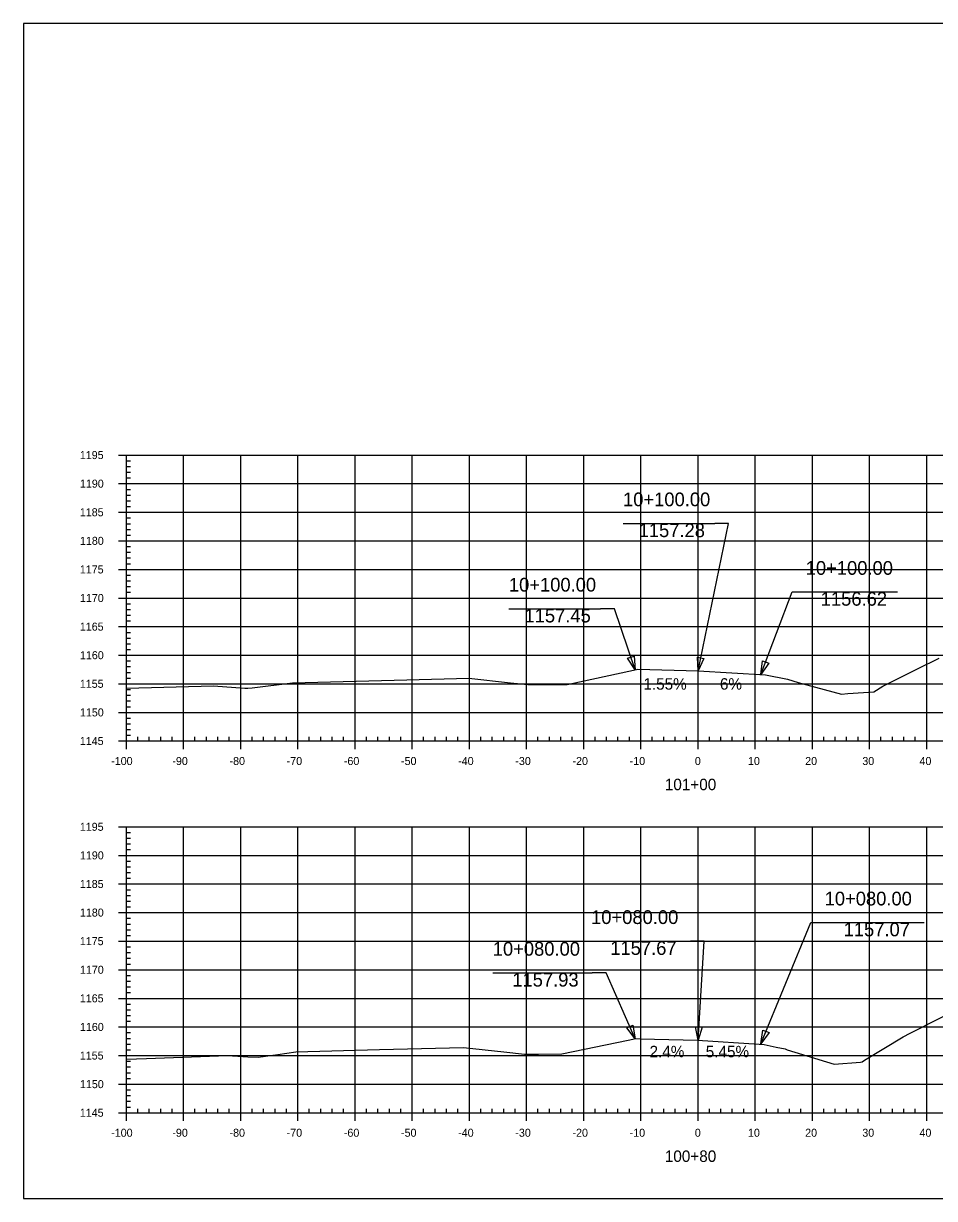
# Model space of a CAD drawing. Extents: x 688474 to 694748, y 765018 to 767373.
# Drawn here: x 689619.8 to 689779.2, y 765584.1 to 765789.5 of the extents above; entities that cross this region are included whole.
import ezdxf

# ---------------------------------------------------------------- set-up
doc = ezdxf.new("R2010")
doc.units = 0
for name, color, linetype in [('60', 7, 'Continuous'), ('Default', 7, 'Continuous'), ('R_Exist Surface', 7, 'Continuous'), ('R_Grid', 7, 'Continuous'), ('R_No Plot', 7, 'Continuous'), ('R_Xsect Slope', 7, 'Continuous')]:
    doc.layers.add(name, color=color, linetype=linetype)

msp = doc.modelspace()

# ---------------------------------------------------------------- linework, layer by layer
at = {"layer": '60'}
for p, q in [((689636.42, 765714.06), (689639.22, 765714.06)), ((689637.82, 765664.06), (689637.82, 765714.06)), ((689637.82, 765713.06), (689638.52, 765713.06)), ((689637.82, 765712.06), (689638.52, 765712.06)), ((689637.82, 765711.06), (689638.52, 765711.06)), ((689636.42, 765709.06), (689639.22, 765709.06)), ((689637.82, 765710.06), (689638.52, 765710.06)), ((689637.82, 765708.06), (689638.52, 765708.06)), ((689637.82, 765707.06), (689638.52, 765707.06)), ((689637.82, 765706.06), (689638.52, 765706.06)), ((689637.82, 765705.06), (689638.52, 765705.06)), ((689636.42, 765704.06), (689639.22, 765704.06)), ((689637.82, 765703.06), (689638.52, 765703.06)), ((689637.82, 765702.06), (689638.52, 765702.06)), ((689637.82, 765701.06), (689638.52, 765701.06)), ((689636.42, 765699.06), (689639.22, 765699.06)), ((689637.82, 765700.06), (689638.52, 765700.06)), ((689637.82, 765698.06), (689638.52, 765698.06)), ((689637.82, 765697.06), (689638.52, 765697.06)), ((689637.82, 765696.06), (689638.52, 765696.06)), ((689636.42, 765694.06), (689639.22, 765694.06)), ((689637.82, 765695.06), (689638.52, 765695.06)), ((689637.82, 765693.06), (689638.52, 765693.06)), ((689637.82, 765692.06), (689638.52, 765692.06)), ((689637.82, 765691.06), (689638.52, 765691.06)), ((689637.82, 765690.06), (689638.52, 765690.06)), ((689636.42, 765689.06), (689639.22, 765689.06)), ((689637.82, 765688.06), (689638.52, 765688.06)), ((689637.82, 765687.06), (689638.52, 765687.06)), ((689637.82, 765686.06), (689638.52, 765686.06)), ((689636.42, 765684.06), (689639.22, 765684.06)), ((689637.82, 765685.06), (689638.52, 765685.06)), ((689637.82, 765683.06), (689638.52, 765683.06)), ((689637.82, 765682.06), (689638.52, 765682.06)), ((689637.82, 765681.06), (689638.52, 765681.06)), ((689637.82, 765680.06), (689638.52, 765680.06)), ((689636.42, 765679.06), (689639.22, 765679.06)), ((689637.82, 765678.06), (689638.52, 765678.06)), ((689637.82, 765677.06), (689638.52, 765677.06)), ((689637.82, 765676.06), (689638.52, 765676.06)), ((689636.42, 765674.06), (689639.22, 765674.06)), ((689637.82, 765675.06), (689638.52, 765675.06)), ((689637.82, 765673.06), (689638.52, 765673.06)), ((689637.82, 765672.06), (689638.52, 765672.06)), ((689637.82, 765671.06), (689638.52, 765671.06)), ((689637.82, 765670.06), (689638.52, 765670.06)), ((689636.42, 765669.06), (689639.22, 765669.06)), ((689637.82, 765668.06), (689638.52, 765668.06)), ((689637.82, 765667.06), (689638.52, 765667.06)), ((689637.82, 765666.06), (689638.52, 765666.06)), ((689637.82, 765662.66), (689637.82, 765665.46)), ((689647.82, 765662.66), (689647.82, 765665.46)), ((689657.82, 765662.66), (689657.82, 765665.46)), ((689667.82, 765662.66), (689667.82, 765665.46)), ((689677.82, 765662.66), (689677.82, 765665.46)), ((689687.82, 765662.66), (689687.82, 765665.46)), ((689697.82, 765662.66), (689697.82, 765665.46)), ((689707.82, 765662.66), (689707.82, 765665.46)), ((689717.82, 765662.66), (689717.82, 765665.46)), ((689727.82, 765662.66), (689727.82, 765665.46)), ((689737.82, 765662.66), (689737.82, 765665.46)), ((689747.82, 765662.66), (689747.82, 765665.46)), ((689757.82, 765662.66), (689757.82, 765665.46)), ((689767.82, 765662.66), (689767.82, 765665.46)), ((689777.82, 765662.66), (689777.82, 765665.46)), ((689636.42, 765664.06), (689639.22, 765664.06)), ((689637.82, 765665.06), (689638.52, 765665.06)), ((689637.82, 765664.06), (689837.82, 765664.06)), ((689639.82, 765664.06), (689639.82, 765664.76)), ((689641.82, 765664.06), (689641.82, 765664.76)), ((689643.82, 765664.06), (689643.82, 765664.76)), ((689645.82, 765664.06), (689645.82, 765664.76)), ((689649.82, 765664.06), (689649.82, 765664.76)), ((689651.82, 765664.06), (689651.82, 765664.76)), ((689653.82, 765664.06), (689653.82, 765664.76)), ((689655.82, 765664.06), (689655.82, 765664.76)), ((689659.82, 765664.06), (689659.82, 765664.76)), ((689661.82, 765664.06), (689661.82, 765664.76)), ((689663.82, 765664.06), (689663.82, 765664.76)), ((689665.82, 765664.06), (689665.82, 765664.76)), ((689669.82, 765664.06), (689669.82, 765664.76)), ((689671.82, 765664.06), (689671.82, 765664.76)), ((689673.82, 765664.06), (689673.82, 765664.76)), ((689675.82, 765664.06), (689675.82, 765664.76)), ((689679.82, 765664.06), (689679.82, 765664.76)), ((689681.82, 765664.06), (689681.82, 765664.76)), ((689683.82, 765664.06), (689683.82, 765664.76)), ((689685.82, 765664.06), (689685.82, 765664.76)), ((689689.82, 765664.06), (689689.82, 765664.76)), ((689691.82, 765664.06), (689691.82, 765664.76)), ((689693.82, 765664.06), (689693.82, 765664.76)), ((689695.82, 765664.06), (689695.82, 765664.76)), ((689699.82, 765664.06), (689699.82, 765664.76)), ((689701.82, 765664.06), (689701.82, 765664.76)), ((689703.82, 765664.06), (689703.82, 765664.76)), ((689705.82, 765664.06), (689705.82, 765664.76)), ((689709.82, 765664.06), (689709.82, 765664.76)), ((689711.82, 765664.06), (689711.82, 765664.76)), ((689713.82, 765664.06), (689713.82, 765664.76)), ((689715.82, 765664.06), (689715.82, 765664.76)), ((689719.82, 765664.06), (689719.82, 765664.76)), ((689721.82, 765664.06), (689721.82, 765664.76)), ((689723.82, 765664.06), (689723.82, 765664.76)), ((689725.82, 765664.06), (689725.82, 765664.76)), ((689729.82, 765664.06), (689729.82, 765664.76)), ((689731.82, 765664.06), (689731.82, 765664.76)), ((689733.82, 765664.06), (689733.82, 765664.76)), ((689735.82, 765664.06), (689735.82, 765664.76)), ((689739.82, 765664.06), (689739.82, 765664.76)), ((689741.82, 765664.06), (689741.82, 765664.76)), ((689743.82, 765664.06), (689743.82, 765664.76)), ((689745.82, 765664.06), (689745.82, 765664.76)), ((689749.82, 765664.06), (689749.82, 765664.76)), ((689751.82, 765664.06), (689751.82, 765664.76)), ((689753.82, 765664.06), (689753.82, 765664.76)), ((689755.82, 765664.06), (689755.82, 765664.76)), ((689759.82, 765664.06), (689759.82, 765664.76)), ((689761.82, 765664.06), (689761.82, 765664.76)), ((689763.82, 765664.06), (689763.82, 765664.76)), ((689765.82, 765664.06), (689765.82, 765664.76)), ((689769.82, 765664.06), (689769.82, 765664.76)), ((689771.82, 765664.06), (689771.82, 765664.76)), ((689773.82, 765664.06), (689773.82, 765664.76)), ((689775.82, 765664.06), (689775.82, 765664.76)), ((689636.42, 765649.06), (689639.22, 765649.06)), ((689637.82, 765599.06), (689637.82, 765649.06)), ((689637.82, 765648.06), (689638.52, 765648.06)), ((689637.82, 765647.06), (689638.52, 765647.06)), ((689637.82, 765646.06), (689638.52, 765646.06)), ((689637.82, 765645.06), (689638.52, 765645.06)), ((689636.42, 765644.06), (689639.22, 765644.06)), ((689637.82, 765643.06), (689638.52, 765643.06)), ((689637.82, 765642.06), (689638.52, 765642.06)), ((689637.82, 765641.06), (689638.52, 765641.06)), ((689636.42, 765639.06), (689639.22, 765639.06)), ((689637.82, 765640.06), (689638.52, 765640.06)), ((689637.82, 765638.06), (689638.52, 765638.06)), ((689637.82, 765637.06), (689638.52, 765637.06)), ((689637.82, 765636.06), (689638.52, 765636.06)), ((689637.82, 765635.06), (689638.52, 765635.06)), ((689636.42, 765634.06), (689639.22, 765634.06)), ((689637.82, 765633.06), (689638.52, 765633.06)), ((689637.82, 765632.06), (689638.52, 765632.06)), ((689637.82, 765631.06), (689638.52, 765631.06)), ((689636.42, 765629.06), (689639.22, 765629.06)), ((689637.82, 765630.06), (689638.52, 765630.06)), ((689637.82, 765628.06), (689638.52, 765628.06)), ((689637.82, 765627.06), (689638.52, 765627.06)), ((689637.82, 765626.06), (689638.52, 765626.06)), ((689637.82, 765625.06), (689638.52, 765625.06)), ((689636.42, 765624.06), (689639.22, 765624.06)), ((689637.82, 765623.06), (689638.52, 765623.06)), ((689637.82, 765622.06), (689638.52, 765622.06)), ((689637.82, 765621.06), (689638.52, 765621.06)), ((689637.82, 765620.06), (689638.52, 765620.06)), ((689636.42, 765619.06), (689639.22, 765619.06)), ((689637.82, 765618.06), (689638.52, 765618.06)), ((689637.82, 765617.06), (689638.52, 765617.06)), ((689637.82, 765616.06), (689638.52, 765616.06)), ((689636.42, 765614.06), (689639.22, 765614.06)), ((689637.82, 765615.06), (689638.52, 765615.06)), ((689637.82, 765613.06), (689638.52, 765613.06)), ((689637.82, 765612.06), (689638.52, 765612.06)), ((689637.82, 765611.06), (689638.52, 765611.06)), ((689637.82, 765610.06), (689638.52, 765610.06)), ((689636.42, 765609.06), (689639.22, 765609.06)), ((689637.82, 765608.06), (689638.52, 765608.06)), ((689637.82, 765607.06), (689638.52, 765607.06)), ((689637.82, 765606.06), (689638.52, 765606.06)), ((689636.42, 765604.06), (689639.22, 765604.06)), ((689637.82, 765605.06), (689638.52, 765605.06)), ((689637.82, 765603.06), (689638.52, 765603.06)), ((689637.82, 765602.06), (689638.52, 765602.06)), ((689637.82, 765601.06), (689638.52, 765601.06)), ((689637.82, 765597.66), (689637.82, 765600.46)), ((689637.82, 765600.06), (689638.52, 765600.06)), ((689639.82, 765599.06), (689639.82, 765599.76)), ((689641.82, 765599.06), (689641.82, 765599.76)), ((689643.82, 765599.06), (689643.82, 765599.76)), ((689645.82, 765599.06), (689645.82, 765599.76)), ((689647.82, 765597.66), (689647.82, 765600.46)), ((689649.82, 765599.06), (689649.82, 765599.76)), ((689651.82, 765599.06), (689651.82, 765599.76)), ((689653.82, 765599.06), (689653.82, 765599.76)), ((689655.82, 765599.06), (689655.82, 765599.76)), ((689657.82, 765597.66), (689657.82, 765600.46)), ((689659.82, 765599.06), (689659.82, 765599.76)), ((689661.82, 765599.06), (689661.82, 765599.76)), ((689663.82, 765599.06), (689663.82, 765599.76)), ((689665.82, 765599.06), (689665.82, 765599.76)), ((689667.82, 765597.66), (689667.82, 765600.46)), ((689669.82, 765599.06), (689669.82, 765599.76)), ((689671.82, 765599.06), (689671.82, 765599.76)), ((689673.82, 765599.06), (689673.82, 765599.76)), ((689675.82, 765599.06), (689675.82, 765599.76)), ((689677.82, 765597.66), (689677.82, 765600.46)), ((689679.82, 765599.06), (689679.82, 765599.76)), ((689681.82, 765599.06), (689681.82, 765599.76)), ((689683.82, 765599.06), (689683.82, 765599.76)), ((689685.82, 765599.06), (689685.82, 765599.76)), ((689687.82, 765597.66), (689687.82, 765600.46)), ((689689.82, 765599.06), (689689.82, 765599.76)), ((689691.82, 765599.06), (689691.82, 765599.76)), ((689693.82, 765599.06), (689693.82, 765599.76)), ((689695.82, 765599.06), (689695.82, 765599.76)), ((689697.82, 765597.66), (689697.82, 765600.46)), ((689699.82, 765599.06), (689699.82, 765599.76)), ((689701.82, 765599.06), (689701.82, 765599.76)), ((689703.82, 765599.06), (689703.82, 765599.76)), ((689705.82, 765599.06), (689705.82, 765599.76)), ((689707.82, 765597.66), (689707.82, 765600.46)), ((689709.82, 765599.06), (689709.82, 765599.76)), ((689711.82, 765599.06), (689711.82, 765599.76)), ((689713.82, 765599.06), (689713.82, 765599.76)), ((689715.82, 765599.06), (689715.82, 765599.76)), ((689717.82, 765597.66), (689717.82, 765600.46)), ((689719.82, 765599.06), (689719.82, 765599.76)), ((689721.82, 765599.06), (689721.82, 765599.76)), ((689723.82, 765599.06), (689723.82, 765599.76)), ((689725.82, 765599.06), (689725.82, 765599.76)), ((689727.82, 765597.66), (689727.82, 765600.46)), ((689729.82, 765599.06), (689729.82, 765599.76)), ((689731.82, 765599.06), (689731.82, 765599.76)), ((689733.82, 765599.06), (689733.82, 765599.76)), ((689735.82, 765599.06), (689735.82, 765599.76)), ((689737.82, 765597.66), (689737.82, 765600.46)), ((689739.82, 765599.06), (689739.82, 765599.76)), ((689741.82, 765599.06), (689741.82, 765599.76)), ((689743.82, 765599.06), (689743.82, 765599.76)), ((689745.82, 765599.06), (689745.82, 765599.76)), ((689747.82, 765597.66), (689747.82, 765600.46)), ((689749.82, 765599.06), (689749.82, 765599.76)), ((689751.82, 765599.06), (689751.82, 765599.76)), ((689753.82, 765599.06), (689753.82, 765599.76)), ((689755.82, 765599.06), (689755.82, 765599.76)), ((689757.82, 765597.66), (689757.82, 765600.46)), ((689759.82, 765599.06), (689759.82, 765599.76)), ((689761.82, 765599.06), (689761.82, 765599.76)), ((689763.82, 765599.06), (689763.82, 765599.76)), ((689765.82, 765599.06), (689765.82, 765599.76)), ((689767.82, 765597.66), (689767.82, 765600.46)), ((689769.82, 765599.06), (689769.82, 765599.76)), ((689771.82, 765599.06), (689771.82, 765599.76)), ((689773.82, 765599.06), (689773.82, 765599.76)), ((689775.82, 765599.06), (689775.82, 765599.76)), ((689777.82, 765597.66), (689777.82, 765600.46)), ((689636.42, 765599.06), (689639.22, 765599.06)), ((689637.82, 765599.06), (689837.82, 765599.06))]:
    msp.add_line(p, q, dxfattribs=at)
at = {"layer": 'R_Exist Surface'}
for p, q in [((689724.7, 765702.11), (689740.75, 765702.11)), ((689756.66, 765690.12), (689772.71, 765690.12)), ((689704.73, 765687.19), (689720.78, 765687.19)), ((689759.97, 765632.31), (689777.39, 765632.31)), ((689719.11, 765629.06), (689736.52, 765629.06)), ((689701.91, 765623.52), (689719.33, 765623.52))]:
    msp.add_line(p, q, dxfattribs=at)
for points in [[(689737.82, 765676.34), (689743.15, 765702.11), (689740.75, 765702.11)], [(689748.82, 765675.68), (689754.26, 765690.12), (689756.66, 765690.12)], [(689726.82, 765676.52), (689723.18, 765687.19), (689720.78, 765687.19)], [(689637.82, 765673.28), (689653.03, 765673.69), (689658.55, 765673.31), (689659.04, 765673.27), (689659.85, 765673.36), (689666.9, 765674.22), (689686.88, 765674.76), (689697.71, 765675.05), (689705, 765674.25), (689708.07, 765673.92), (689712.74, 765673.93), (689714.95, 765673.92), (689726.53, 765676.45), (689727.27, 765676.61), (689737.82, 765676.34), (689749.65, 765675.63), (689749.65, 765675.63), (689753.45, 765674.85), (689755.33, 765674.28), (689762.91, 765672.26), (689764.04, 765672.35), (689768.57, 765672.67), (689770.15, 765673.63), (689776.24, 765676.65), (689780, 765678.55)], [(689748.82, 765611.13), (689757.57, 765632.31), (689759.97, 765632.31)], [(689737.82, 765611.73), (689738.92, 765629.06), (689736.52, 765629.06)], [(689726.82, 765611.99), (689721.73, 765623.52), (689719.33, 765623.52)], [(689637.82, 765608.4), (689641.32, 765608.55), (689655.51, 765609.05), (689659.04, 765608.86), (689660.9, 765608.79), (689664.34, 765609.24), (689667.46, 765609.68), (689682.09, 765610.09), (689696.81, 765610.49), (689703.82, 765609.71), (689707.49, 765609.31), (689709.91, 765609.32), (689714, 765609.35), (689725.62, 765611.74), (689726.95, 765612.02), (689727.72, 765612), (689737.7, 765611.74), (689748.53, 765611.06), (689749.37, 765611.01), (689751.49, 765610.55), (689753.05, 765610.21), (689753.43, 765610.07), (689761.61, 765607.57), (689766.24, 765607.92), (689766.51, 765607.94), (689766.96, 765608.27), (689773.73, 765612.35), (689774.93, 765612.96), (689790.39, 765620.76)]]:
    msp.add_lwpolyline(points, dxfattribs=at)
for points in [[(689726.82, 765676.52), (689725.51, 765678.53), (689726.62, 765678.91)], [(689737.82, 765676.34), (689737.72, 765678.74), (689738.86, 765678.5)], [(689748.82, 765675.68), (689749.09, 765678.07), (689750.18, 765677.66)], [(689726.82, 765611.99), (689725.34, 765613.89), (689726.41, 765614.36)], [(689737.82, 765611.73), (689737.38, 765614.09), (689738.55, 765614.02)], [(689748.82, 765611.13), (689749.17, 765613.5), (689750.24, 765613.06)]]:
    msp.add_lwpolyline(points, close=True, dxfattribs=at)
at = {"layer": 'R_Grid'}
for p, q in [((689637.82, 765714.06), (689837.82, 765714.06)), ((689637.82, 765664.06), (689637.82, 765714.06)), ((689647.82, 765664.06), (689647.82, 765714.06)), ((689657.82, 765664.06), (689657.82, 765714.06)), ((689667.82, 765664.06), (689667.82, 765714.06)), ((689677.82, 765664.06), (689677.82, 765714.06)), ((689687.82, 765664.06), (689687.82, 765714.06)), ((689697.82, 765664.06), (689697.82, 765714.06)), ((689707.82, 765664.06), (689707.82, 765714.06)), ((689717.82, 765664.06), (689717.82, 765714.06)), ((689727.82, 765664.06), (689727.82, 765714.06)), ((689737.82, 765664.06), (689737.82, 765714.06)), ((689747.82, 765664.06), (689747.82, 765714.06)), ((689757.82, 765664.06), (689757.82, 765714.06)), ((689767.82, 765664.06), (689767.82, 765714.06)), ((689777.82, 765664.06), (689777.82, 765714.06)), ((689637.82, 765709.06), (689837.82, 765709.06)), ((689637.82, 765704.06), (689837.82, 765704.06)), ((689637.82, 765699.06), (689837.82, 765699.06)), ((689637.82, 765694.06), (689837.82, 765694.06)), ((689637.82, 765689.06), (689837.82, 765689.06)), ((689637.82, 765684.06), (689837.82, 765684.06)), ((689637.82, 765679.06), (689837.82, 765679.06)), ((689637.82, 765674.06), (689837.82, 765674.06)), ((689637.82, 765669.06), (689837.82, 765669.06)), ((689637.82, 765664.06), (689837.82, 765664.06)), ((689637.82, 765649.06), (689837.82, 765649.06)), ((689637.82, 765599.06), (689637.82, 765649.06)), ((689647.82, 765599.06), (689647.82, 765649.06)), ((689657.82, 765599.06), (689657.82, 765649.06)), ((689667.82, 765599.06), (689667.82, 765649.06)), ((689677.82, 765599.06), (689677.82, 765649.06)), ((689687.82, 765599.06), (689687.82, 765649.06)), ((689697.82, 765599.06), (689697.82, 765649.06)), ((689707.82, 765599.06), (689707.82, 765649.06)), ((689717.82, 765599.06), (689717.82, 765649.06)), ((689727.82, 765599.06), (689727.82, 765649.06)), ((689737.82, 765599.06), (689737.82, 765649.06)), ((689747.82, 765599.06), (689747.82, 765649.06)), ((689757.82, 765599.06), (689757.82, 765649.06)), ((689767.82, 765599.06), (689767.82, 765649.06)), ((689777.82, 765599.06), (689777.82, 765649.06)), ((689637.82, 765644.06), (689837.82, 765644.06)), ((689637.82, 765639.06), (689837.82, 765639.06)), ((689637.82, 765634.06), (689837.82, 765634.06)), ((689637.82, 765629.06), (689837.82, 765629.06)), ((689637.82, 765624.06), (689837.82, 765624.06)), ((689637.82, 765619.06), (689837.82, 765619.06)), ((689637.82, 765614.06), (689837.82, 765614.06)), ((689637.82, 765609.06), (689837.82, 765609.06)), ((689637.82, 765604.06), (689837.82, 765604.06)), ((689637.82, 765599.06), (689837.82, 765599.06))]:
    msp.add_line(p, q, dxfattribs=at)
at = {"layer": 'R_No Plot'}
msp.add_lwpolyline([(689619.82, 765584.06), (689936, 765584.06), (689936, 765789.52), (689619.82, 765789.52)], close=True, dxfattribs=at)

# ---------------------------------------------------------------- texts
at = {"layer": '60'}
for s, height, p in [('1195', 1.4, (689629.67, 765713.36)), ('1190', 1.4, (689629.69, 765708.36)), ('1185', 1.4, (689629.67, 765703.36)), ('1180', 1.4, (689629.69, 765698.36)), ('1175', 1.4, (689629.67, 765693.36)), ('1170', 1.4, (689629.69, 765688.36)), ('1165', 1.4, (689629.67, 765683.36)), ('1160', 1.4, (689629.69, 765678.36)), ('1155', 1.4, (689629.67, 765673.36)), ('1150', 1.4, (689629.69, 765668.36)), ('1145', 1.4, (689629.67, 765663.36)), ('-100', 1.4, (689635.16, 765659.86)), ('-90', 1.4, (689645.86, 765659.86)), ('-80', 1.4, (689655.86, 765659.86)), ('-70', 1.4, (689665.86, 765659.86)), ('-60', 1.4, (689675.86, 765659.86)), ('-50', 1.4, (689685.86, 765659.86)), ('-40', 1.4, (689695.86, 765659.86)), ('-30', 1.4, (689705.86, 765659.86)), ('-20', 1.4, (689715.86, 765659.86)), ('-10', 1.4, (689725.86, 765659.86)), ('0', 1.4, (689737.26, 765659.86)), ('10', 1.4, (689746.56, 765659.86)), ('20', 1.4, (689756.56, 765659.86)), ('30', 1.4, (689766.56, 765659.86)), ('40', 1.4, (689776.56, 765659.86)), ('101+00', 2, (689732.01, 765655.46)), ('1195', 1.4, (689629.67, 765648.36)), ('1190', 1.4, (689629.69, 765643.36)), ('1185', 1.4, (689629.67, 765638.36)), ('1180', 1.4, (689629.69, 765633.36)), ('1175', 1.4, (689629.67, 765628.36)), ('1170', 1.4, (689629.69, 765623.36)), ('1165', 1.4, (689629.67, 765618.36)), ('1160', 1.4, (689629.69, 765613.36)), ('1155', 1.4, (689629.67, 765608.36)), ('1150', 1.4, (689629.69, 765603.36)), ('1145', 1.4, (689629.67, 765598.36)), ('-100', 1.4, (689635.16, 765594.86)), ('-90', 1.4, (689645.86, 765594.86)), ('-80', 1.4, (689655.86, 765594.86)), ('-70', 1.4, (689665.86, 765594.86)), ('-60', 1.4, (689675.86, 765594.86)), ('-50', 1.4, (689685.86, 765594.86)), ('-40', 1.4, (689695.86, 765594.86)), ('-30', 1.4, (689705.86, 765594.86)), ('-20', 1.4, (689715.86, 765594.86)), ('-10', 1.4, (689725.86, 765594.86)), ('0', 1.4, (689737.26, 765594.86)), ('10', 1.4, (689746.56, 765594.86)), ('20', 1.4, (689756.56, 765594.86)), ('30', 1.4, (689766.56, 765594.86)), ('40', 1.4, (689776.56, 765594.86)), ('100+80', 2, (689732.01, 765590.46))]:
    msp.add_text(s, height=height, dxfattribs=at).set_placement(p)
at = {"layer": 'Default'}
for s, p in [('1.55%', (689728.26, 765673.04)), ('6%', (689741.65, 765673.04)), ('2.4%', (689729.34, 765608.76)), ('5.45%', (689739.17, 765608.76))]:
    msp.add_text(s, height=2, dxfattribs=at).set_placement(p)
at = {"layer": 'R_Xsect Slope'}
for s, p in [('10+100.00', (689724.7, 765705.11)), ('1157.28', (689727.43, 765699.71)), ('10+100.00', (689756.66, 765693.12)), ('10+100.00', (689704.73, 765690.19)), ('1156.62', (689759.28, 765687.72)), ('1157.45', (689707.46, 765684.79)), ('10+080.00', (689759.97, 765635.31)), ('10+080.00', (689719.11, 765632.06)), ('1157.07', (689763.29, 765629.91)), ('10+080.00', (689701.91, 765626.52)), ('1157.67', (689722.47, 765626.66)), ('1157.93', (689705.33, 765621.12))]:
    msp.add_text(s, height=2.4, dxfattribs=at).set_placement(p)

doc.saveas('drawing.dxf')
